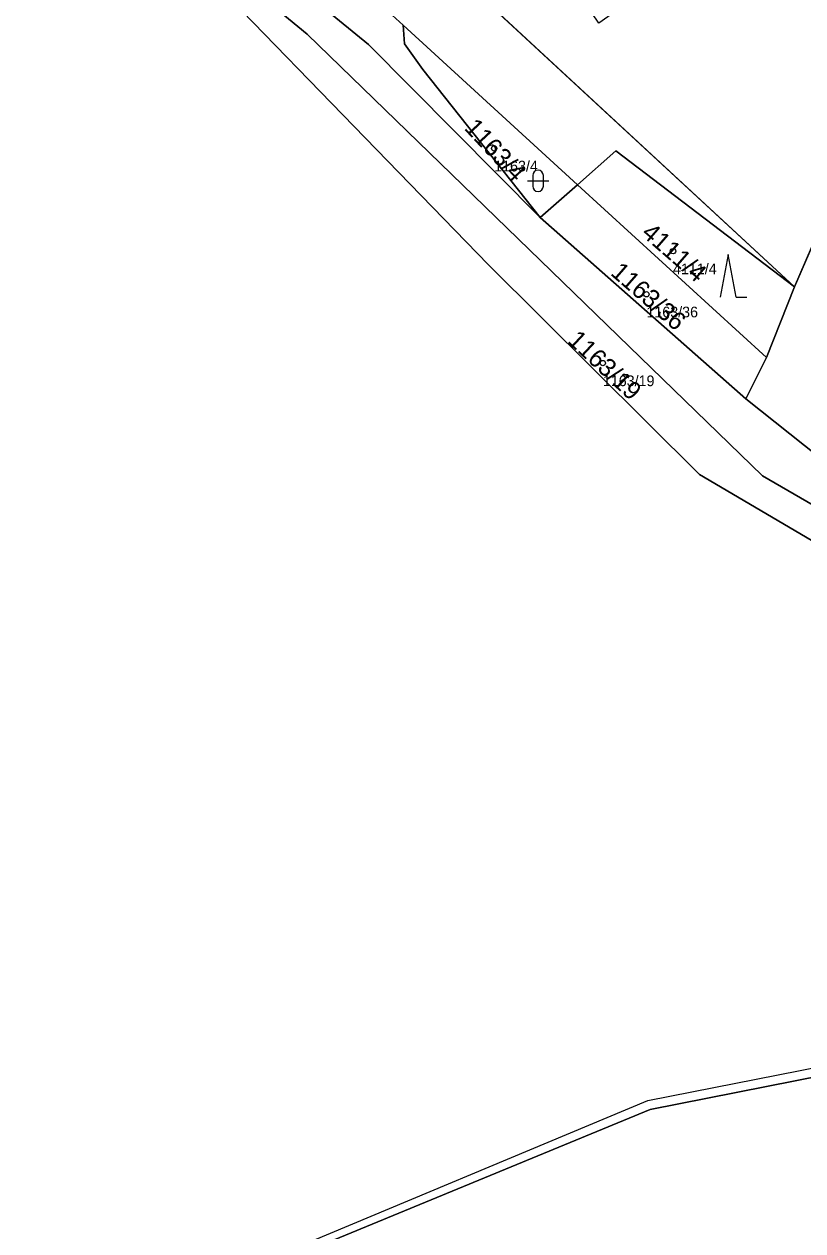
# Model space of a CAD drawing. Extents: x -754150 to -749824, y -1058608 to -1053956.
# Drawn here: x -753577.7 to -753504.7, y -1056644.5 to -1056531.4 of the extents above; entities that cross this region are included whole.
import ezdxf

# ---------------------------------------------------------------- set-up
doc = ezdxf.new("R2010")
doc.units = 0
for name, color, linetype in [('Vrstva 1', 7, 'Continuous'), ('Vrstva 2', 7, 'Continuous'), ('Vrstva 3', 7, 'Continuous'), ('Vrstva 4', 7, 'Continuous'), ('Vrstva 50', 7, 'Continuous'), ('Vrstva 51', 7, 'Continuous')]:
    doc.layers.add(name, color=color, linetype=linetype)

msp = doc.modelspace()

# ---------------------------------------------------------------- linework, layer by layer
at = {"layer": 'Vrstva 1'}
for p, q in [((-753505.53, -1056556.02), (-753593.43, -1056474.65)), ((-753525.85, -1056546.44), (-753542.17, -1056531.5)), ((-753495.55, -1056532.95), (-753505.53, -1056556.02)), ((-753529.34, -1056549.53), (-753525.85, -1056546.44)), ((-753525.85, -1056546.44), (-753508.15, -1056562.64)), ((-753510.07, -1056566.51), (-753529.34, -1056549.53)), ((-753505.53, -1056556.02), (-753508.15, -1056562.64)), ((-753508.15, -1056562.64), (-753510.07, -1056566.51)), ((-753510.07, -1056566.51), (-753496.34, -1056577.44))]:
    msp.add_line(p, q, dxfattribs=at)
for points in [[(-753529.34, -1056549.53), (-753545.42, -1056533.3), (-753583.33, -1056502.36)], [(-753453.07, -1056600.3), (-753472.8, -1056598.08), (-753514.42, -1056573.59), (-753534.17, -1056553.96), (-753570.93, -1056516.05)], [(-753570.93, -1056516.05), (-753551.16, -1056532.34), (-753508.51, -1056573.72), (-753473.23, -1056594.16), (-753463.1, -1056597.99), (-753453.07, -1056600.3)], [(-753551.16, -1056522.42), (-753543.9, -1056529.92), (-753542.17, -1056531.5)], [(-753542.17, -1056531.5), (-753542.04, -1056533.25), (-753540.34, -1056535.66), (-753529.34, -1056549.53)], [(-753525.85, -1056546.44), (-753522.27, -1056543.28), (-753505.53, -1056556.02)], [(-753560.61, -1056650.24), (-753519.03, -1056633.09), (-753502.77, -1056629.89), (-753471.63, -1056633.49), (-753427.67, -1056630.48), (-753407.19, -1056627.88)]]:
    msp.add_lwpolyline(points, dxfattribs=at)
at = {"layer": 'Vrstva 3'}
for p, q in [((-753530.54, -1056546.08), (-753528.54, -1056546.08)), ((-753530.04, -1056545.58), (-753530.04, -1056546.58)), ((-753529.04, -1056546.58), (-753529.04, -1056545.58)), ((-753511.72, -1056552.97), (-753512.47, -1056556.97)), ((-753510.97, -1056556.97), (-753511.72, -1056552.97)), ((-753510.97, -1056556.97), (-753509.97, -1056556.97))]:
    msp.add_line(p, q, dxfattribs=at)
for centre, start, end in [((-753529.54, -1056545.58), 0, 180), ((-753529.54, -1056546.58), 180, 359.9879)]:
    msp.add_arc(centre, 0.5, start, end, dxfattribs=at)
at = {"layer": 'Vrstva 4'}
for p, q in [((-753519.25, -1056632.27), (-753502.92, -1056629.05)), ((-753576.6, -1056656.21), (-753519.25, -1056632.27))]:
    msp.add_line(p, q, dxfattribs=at)
at = {"layer": 'Vrstva 50'}
for centre in [(-753533.65, -1056543.04), (-753516.9, -1056552.67), (-753519.39, -1056556.71), (-753523.47, -1056563.16)]:
    msp.add_circle(centre, 0.25, dxfattribs=at)
at = {"layer": 'Vrstva 51'}
for points in [[(-753487.13, -1056505.35), (-753523.85, -1056531.29), (-753531.35, -1056520.23), (-753489.13, -1056491.7), (-753484.8, -1056497.7), (-753465.94, -1056435.85), (-753564.64, -1056466.66), (-753593.43, -1056474.65), (-753505.53, -1056556.02), (-753495.55, -1056532.95)], [(-753522.27, -1056543.28), (-753505.53, -1056556.02), (-753593.43, -1056474.65), (-753574.51, -1056498.55), (-753566.21, -1056507.96), (-753564.66, -1056508.48), (-753551.16, -1056522.42), (-753543.9, -1056529.92), (-753542.17, -1056531.5), (-753525.85, -1056546.44)], [(-753583.33, -1056502.36), (-753545.42, -1056533.3), (-753529.34, -1056549.53), (-753540.34, -1056535.66), (-753542.04, -1056533.25), (-753542.17, -1056531.5), (-753543.9, -1056529.92), (-753551.16, -1056522.42), (-753552.77, -1056522.22), (-753555.95, -1056519.59), (-753566.21, -1056507.96)], [(-753453.07, -1056600.3), (-753463.1, -1056597.99), (-753473.23, -1056594.16), (-753508.51, -1056573.72), (-753551.16, -1056532.34), (-753570.93, -1056516.05), (-753534.17, -1056553.96), (-753514.42, -1056573.59), (-753472.8, -1056598.08)], [(-753525.85, -1056546.44), (-753542.17, -1056531.5), (-753542.04, -1056533.25), (-753540.34, -1056535.66), (-753529.34, -1056549.53)], [(-753505.53, -1056556.02), (-753508.15, -1056562.64), (-753510.07, -1056566.51), (-753496.34, -1056577.44), (-753494.76, -1056572.91), (-753494.15, -1056571.16), (-753483.26, -1056539.96), (-753482.2, -1056536.9), (-753495.55, -1056532.95)], [(-753525.85, -1056546.44), (-753508.15, -1056562.64), (-753505.53, -1056556.02), (-753522.27, -1056543.28)], [(-753510.07, -1056566.51), (-753508.15, -1056562.64), (-753525.85, -1056546.44), (-753529.34, -1056549.53)], [(-753265.56, -1056663.39), (-753276.16, -1056653.97), (-753278.82, -1056650.56), (-753292.77, -1056645.7), (-753335.25, -1056635.87), (-753366.72, -1056630.99), (-753406.2, -1056627.98), (-753407.19, -1056627.88), (-753427.67, -1056630.48), (-753471.63, -1056633.49), (-753502.77, -1056629.89), (-753519.03, -1056633.09), (-753560.61, -1056650.24), (-753509.56, -1056775.68), (-753408.19, -1056734.86), (-753306.4, -1056693.88), (-753275.18, -1056681.3), (-753268.6, -1056670.16), (-753263.41, -1056667.25)]]:
    msp.add_lwpolyline(points, close=True, dxfattribs=at)
for points in [[(-753380.45, -1056597.89), (-753404.15, -1056597.73), (-753438.16, -1056598.18), (-753447.53, -1056595.64), (-753452.88, -1056594.38), (-753455, -1056595.3), (-753463.78, -1056593.32), (-753468.64, -1056592.17), (-753470.78, -1056591.42), (-753473.53, -1056590.82), (-753487.19, -1056584.79), (-753496.34, -1056577.44), (-753510.07, -1056566.51), (-753529.34, -1056549.53), (-753545.42, -1056533.3), (-753583.33, -1056502.36), (-753606.28, -1056494.86), (-753618.26, -1056495.81), (-753636.51, -1056497.25), (-753672.94, -1056503.58)], [(-753681.99, -1056506.16), (-753655.63, -1056504.44), (-753613.4, -1056496.82), (-753583.64, -1056505.94), (-753570.93, -1056516.05), (-753551.16, -1056532.34), (-753508.51, -1056573.72), (-753473.23, -1056594.16), (-753463.1, -1056597.99), (-753453.07, -1056600.3), (-753437.03, -1056602.11), (-753404.68, -1056602.15), (-753399.68, -1056602.52)], [(-753699.71, -1056712.65), (-753653.78, -1056690), (-753624.73, -1056671.76), (-753606.48, -1056663.75), (-753576.38, -1056656.74), (-753560.61, -1056650.24), (-753519.03, -1056633.09), (-753502.77, -1056629.89), (-753471.63, -1056633.49), (-753427.67, -1056630.48), (-753407.19, -1056627.88), (-753405.47, -1056609.26), (-753405.39, -1056608.35), (-753405.26, -1056606.92), (-753414.71, -1056604.62), (-753437.03, -1056602.11), (-753453.07, -1056600.3), (-753472.8, -1056598.08), (-753514.42, -1056573.59), (-753534.17, -1056553.96), (-753570.93, -1056516.05), (-753607.06, -1056501.27), (-753655.63, -1056504.44), (-753681.99, -1056506.16)]]:
    msp.add_lwpolyline(points, dxfattribs=at)

# ---------------------------------------------------------------- texts
at = {"layer": 'Vrstva 2'}
for s, rotation, p in [('1163/4', 313, (-753536.53, -1056541.2)), ('4111/4', 319, (-753519.95, -1056551.14)), ('1163/36', 319, (-753522.84, -1056554.83)), ('1163/19', 317, (-753526.86, -1056561.16))]:
    msp.add_text(s, height=1.7, rotation=rotation, dxfattribs=at).set_placement(p)
at = {"layer": 'Vrstva 50'}
for s, p in [('1163/4', (-753533.65, -1056545.2)), ('4111/4', (-753516.9, -1056554.83)), ('1163/36', (-753519.39, -1056558.87)), ('1163/19', (-753523.47, -1056565.32))]:
    msp.add_text(s, height=1, dxfattribs=at).set_placement(p)

doc.saveas('drawing.dxf')
